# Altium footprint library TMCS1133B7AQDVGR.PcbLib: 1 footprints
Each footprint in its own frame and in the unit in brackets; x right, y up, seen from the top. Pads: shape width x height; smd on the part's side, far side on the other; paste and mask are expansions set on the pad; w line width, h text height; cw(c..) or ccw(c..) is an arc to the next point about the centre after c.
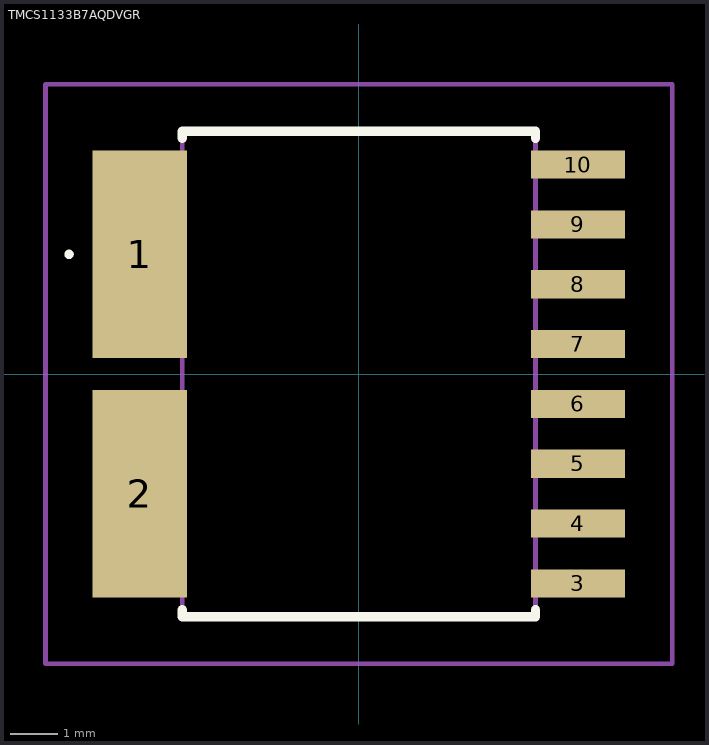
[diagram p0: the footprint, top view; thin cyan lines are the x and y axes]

## TMCS1133B7AQDVGR [mm]
pads (10):
  rect 2x4.41 smd: 1(-4.65,2.54) 2(-4.65,-2.54)
  rect 2x0.6 smd: 3(4.65,-4.445) 4(4.65,-3.175) 5(4.65,-1.905) 6(4.65,-0.635) 7(4.65,0.635) 8(4.65,1.905) 9(4.65,3.175) 10(4.65,4.445)
Top Overlay:
  lines w0.1: -6.2,2.54 -6.2,2.54 ; -6.2,2.54 ccw(c-6.15,2.54) -6.1,2.54 ; -6.2,2.54 cw(c-6.15,2.54) -6.1,2.54 ; -6.1,2.54 -6.1,2.54
  lines w0.2: -3.75,-5 -3.75,-5.15 3.75,-5.15 3.75,-5 ; -3.75,5 -3.75,5.15 3.75,5.15 3.75,5
Mechanical 15:
  lines w0.1: -3.75,-5.15 3.75,-5.15 3.75,5.15 -3.75,5.15 -3.75,-5.15
Mechanical 20:
  lines w0.1: -6.65,-6.15 6.65,-6.15 6.65,6.15 -6.65,6.15 -6.65,-6.15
